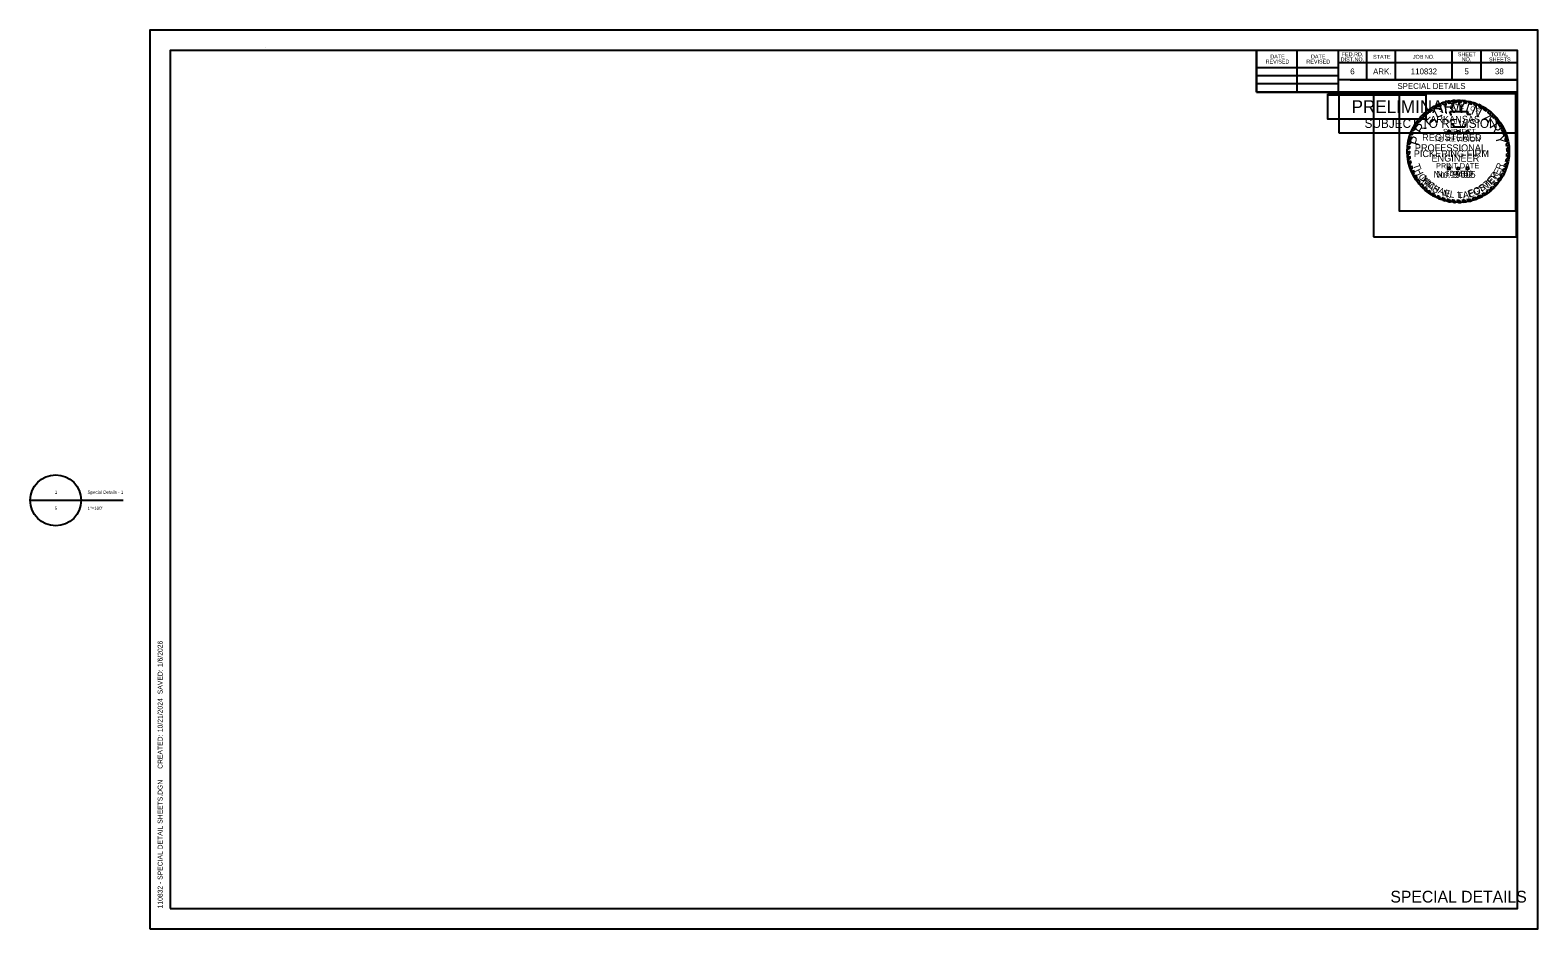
# Model space of a CAD drawing. Extents: x -0.12 to 1.42, y 0 to 0.92.
import ezdxf

# ---------------------------------------------------------------- set-up
doc = ezdxf.new("R2010")
doc.units = 0
for name, color, linetype in [('Default', 7, 'Continuous'), ('DSN_DRFT_Guideline-No-Plot', 7, 'Continuous'), ('SHET_Annotations', 7, 'Continuous'), ('SHET_Border-Lines', 7, 'Continuous'), ('SHET_Border-Text', 7, 'Continuous'), ('SHET_Stamp-Prelim', 7, 'Continuous'), ('SHET_Stamp-Seal', 7, 'Continuous'), ('STAMP_PE DIG SIG', 7, 'Continuous'), ('STAMP_PE_BACKGROUND', 7, 'Continuous'), ('STAMP_PE_FOSTER', 7, 'Continuous'), ('STAMP_PE_SEAL-INFO', 7, 'Continuous'), ('STAMP_PE_TAEGTMEYER', 7, 'Continuous'), ('STAMP_PRELIMINARY', 7, 'Continuous')]:
    doc.layers.add(name, color=color, linetype=linetype)

msp = doc.modelspace()

# ---------------------------------------------------------------- linework, layer by layer
at = {"layer": 'Default'}
for p, q in [((-0.1223, 0.4371), (-0.0702, 0.4371)), ((-0.096, 0.4371), (-0.0272, 0.4371))]:
    msp.add_line(p, q, dxfattribs=at)
msp.add_circle((-0.0962, 0.4371), 0.026, dxfattribs=at)
at = {"layer": 'DSN_DRFT_Guideline-No-Plot'}
msp.add_lwpolyline([(0, 0), (1.4167, 0), (1.4167, 0.9167), (0, 0.9167)], close=True, dxfattribs=at)
at = {"layer": 'SHET_Border-Lines'}
for p, q in [((0.1176, 0.8988), (0.1176, 0.8988)), ((0.1176, 0.8988), (0.1176, 0.8988)), ((1.1296, 0.8534), (1.1296, 0.8958)), ((1.1711, 0.8534), (1.1711, 0.8958)), ((1.2127, 0.8958), (1.2127, 0.8534)), ((1.2417, 0.8958), (1.2417, 0.866)), ((1.2712, 0.8958), (1.2712, 0.866)), ((1.3289, 0.8958), (1.3289, 0.866)), ((1.3584, 0.8958), (1.3584, 0.866)), ((1.1296, 0.8786), (1.2127, 0.8786)), ((1.3958, 0.8832), (1.2127, 0.8832)), ((1.3958, 0.8833), (1.3958, 0.8833)), ((1.1296, 0.8706), (1.2127, 0.8706)), ((1.1296, 0.8622), (1.2127, 0.8622)), ((1.3958, 0.866), (1.2127, 0.866)), ((1.2252, 0.866), (1.3958, 0.866)), ((1.3958, 0.8534), (1.1296, 0.8534))]:
    msp.add_line(p, q, dxfattribs=at)
for points in [[(0.0208, 0.0208), (1.3958, 0.0208), (1.3958, 0.8958), (0.0208, 0.8958)], [(1.1296, 0.8534), (1.3958, 0.8534), (1.3958, 0.8958), (1.1296, 0.8958)]]:
    msp.add_lwpolyline(points, close=True, dxfattribs=at)
at = {"layer": 'SHET_Stamp-Prelim'}
msp.add_lwpolyline([(1.2137, 0.8119), (1.3948, 0.8119), (1.3948, 0.8524), (1.2137, 0.8524)], close=True, dxfattribs=at)
at = {"layer": 'SHET_Stamp-Seal'}
msp.add_line((1.3219, 0.7895), (1.3219, 0.7895), dxfattribs=at)
msp.add_lwpolyline([(1.249, 0.7057), (1.3948, 0.7057), (1.3948, 0.8524), (1.249, 0.8524)], close=True, dxfattribs=at)
at = {"layer": 'STAMP_PE DIG SIG'}
msp.add_lwpolyline([(1.2022, 0.8508), (1.3022, 0.8508), (1.3022, 0.8258), (1.2022, 0.8258)], close=True, dxfattribs=at)
at = {"layer": 'STAMP_PE_BACKGROUND'}
for points in [[(1.2022, 0.8517), (1.3022, 0.8517), (1.3022, 0.8258), (1.2022, 0.8258)], [(1.3942, 0.8517), (1.275, 0.8517), (1.275, 0.7325), (1.3942, 0.7325)]]:
    msp.add_lwpolyline(points, close=True, dxfattribs=at)
at = {"layer": 'STAMP_PE_SEAL-INFO'}
for p, q in [((1.3002, 0.8313), (1.3028, 0.8306)), ((1.3021, 0.833), (1.3051, 0.8325)), ((1.3042, 0.8348), (1.3068, 0.8337)), ((1.3066, 0.8363), (1.309, 0.8352)), ((1.3087, 0.8377), (1.3112, 0.8365)), ((1.3112, 0.8391), (1.3138, 0.8378)), ((1.3137, 0.8403), (1.3158, 0.8387)), ((1.3165, 0.8415), (1.3181, 0.8397)), ((1.3184, 0.8422), (1.3206, 0.8405)), ((1.3217, 0.8432), (1.3233, 0.8413)), ((1.3239, 0.8438), (1.3259, 0.8418)), ((1.3266, 0.8443), (1.3283, 0.8422)), ((1.3269, 0.8337), (1.3456, 0.8337)), ((1.3276, 0.832), (1.3269, 0.8337)), ((1.3281, 0.8303), (1.3276, 0.832)), ((1.3295, 0.8447), (1.331, 0.8426)), ((1.3336, 0.8427), (1.3318, 0.8449)), ((1.3364, 0.8428), (1.3348, 0.845)), ((1.3389, 0.8426), (1.3375, 0.845)), ((1.3417, 0.8424), (1.3401, 0.8448)), ((1.3441, 0.842), (1.3427, 0.8445)), ((1.3456, 0.8337), (1.3443, 0.831)), ((1.3473, 0.8413), (1.3463, 0.8439)), ((1.3495, 0.8407), (1.3486, 0.8433)), ((1.352, 0.8399), (1.3512, 0.8426)), ((1.3544, 0.839), (1.3536, 0.8418)), ((1.357, 0.8379), (1.3564, 0.8406)), ((1.3594, 0.8366), (1.359, 0.8394)), ((1.3616, 0.8353), (1.3614, 0.8381)), ((1.364, 0.8337), (1.3639, 0.8366)), ((1.366, 0.8322), (1.3662, 0.8349)), ((1.3685, 0.8301), (1.3687, 0.8331)), ((1.3703, 0.8285), (1.3707, 0.8313)), ((1.2891, 0.8167), (1.2918, 0.8171)), ((1.2904, 0.8191), (1.2931, 0.8192)), ((1.2917, 0.8213), (1.2946, 0.8215)), ((1.293, 0.8232), (1.2959, 0.8232)), ((1.2946, 0.8253), (1.2977, 0.8254)), ((1.2965, 0.8276), (1.2994, 0.8274)), ((1.2983, 0.8295), (1.3014, 0.8293)), ((1.3282, 0.8297), (1.3281, 0.8303)), ((1.3293, 0.8201), (1.3291, 0.8213)), ((1.331, 0.8201), (1.3293, 0.8201)), ((1.331, 0.8177), (1.331, 0.8201)), ((1.3423, 0.8177), (1.331, 0.8177)), ((1.3424, 0.8196), (1.3423, 0.8177)), ((1.3429, 0.8213), (1.3424, 0.8196)), ((1.3443, 0.831), (1.3478, 0.831)), ((1.3478, 0.831), (1.347, 0.8297)), ((1.3723, 0.8264), (1.3727, 0.8294)), ((1.3738, 0.8247), (1.3746, 0.8273)), ((1.3756, 0.8223), (1.3764, 0.8251)), ((1.3769, 0.8206), (1.3779, 0.8232)), ((1.3786, 0.8178), (1.3796, 0.8205)), ((1.3797, 0.8157), (1.381, 0.8182)), ((1.381, 0.813), (1.3823, 0.8157)), ((1.2862, 0.8008), (1.2838, 0.7996)), ((1.2867, 0.8034), (1.2841, 0.802)), ((1.2847, 0.8048), (1.2873, 0.8059)), ((1.2853, 0.8071), (1.2879, 0.808)), ((1.2862, 0.8099), (1.2889, 0.8106)), ((1.287, 0.8121), (1.2898, 0.8129)), ((1.288, 0.8145), (1.2908, 0.8151)), ((1.3252, 0.8129), (1.3241, 0.8137)), ((1.3241, 0.8137), (1.3255, 0.8137)), ((1.3248, 0.8116), (1.3252, 0.8129)), ((1.3259, 0.8124), (1.3248, 0.8116)), ((1.3255, 0.8137), (1.3259, 0.815)), ((1.3259, 0.815), (1.3264, 0.8137)), ((1.327, 0.8116), (1.3259, 0.8124)), ((1.3264, 0.8137), (1.3277, 0.8137)), ((1.3277, 0.8137), (1.3266, 0.8129)), ((1.3266, 0.8129), (1.327, 0.8116)), ((1.3347, 0.8129), (1.3336, 0.8137)), ((1.3336, 0.8137), (1.335, 0.8137)), ((1.3343, 0.8116), (1.3347, 0.8129)), ((1.3354, 0.8124), (1.3343, 0.8116)), ((1.335, 0.8137), (1.3354, 0.815)), ((1.3354, 0.815), (1.3358, 0.8137)), ((1.3365, 0.8116), (1.3354, 0.8124)), ((1.3358, 0.8137), (1.3372, 0.8137)), ((1.3372, 0.8137), (1.3361, 0.8129)), ((1.3361, 0.8129), (1.3365, 0.8116)), ((1.3442, 0.8129), (1.3431, 0.8137)), ((1.3431, 0.8137), (1.3445, 0.8137)), ((1.3438, 0.8116), (1.3442, 0.8129)), ((1.3449, 0.8124), (1.3438, 0.8116)), ((1.3445, 0.8137), (1.3449, 0.815)), ((1.3449, 0.815), (1.3453, 0.8137)), ((1.346, 0.8116), (1.3449, 0.8124)), ((1.3453, 0.8137), (1.3467, 0.8137)), ((1.3467, 0.8137), (1.3456, 0.8129)), ((1.3456, 0.8129), (1.346, 0.8116)), ((1.3818, 0.8112), (1.3832, 0.8136)), ((1.3829, 0.8081), (1.3844, 0.8107)), ((1.3835, 0.8061), (1.3851, 0.8086)), ((1.3842, 0.8029), (1.386, 0.8054)), ((1.3846, 0.8008), (1.3866, 0.8028)), ((1.2857, 0.796), (1.2834, 0.7946)), ((1.2856, 0.7933), (1.2834, 0.7914)), ((1.2859, 0.7984), (1.2835, 0.7968)), ((1.2857, 0.791), (1.2835, 0.7892)), ((1.2858, 0.7882), (1.2838, 0.7862)), ((1.2861, 0.7858), (1.2842, 0.7837)), ((1.3846, 0.7855), (1.3871, 0.7867)), ((1.3849, 0.7876), (1.3874, 0.7891)), ((1.385, 0.798), (1.387, 0.7998)), ((1.3851, 0.7956), (1.3873, 0.7973)), ((1.3852, 0.7927), (1.3875, 0.7945)), ((1.3852, 0.7905), (1.3875, 0.792)), ((1.2866, 0.7833), (1.2847, 0.7812)), ((1.2871, 0.7809), (1.2854, 0.7786)), ((1.2878, 0.7784), (1.2861, 0.7761)), ((1.2886, 0.7761), (1.287, 0.7738)), ((1.2895, 0.7737), (1.288, 0.7713)), ((1.2905, 0.7715), (1.2892, 0.769)), ((1.3252, 0.7754), (1.3241, 0.7763)), ((1.3241, 0.7763), (1.3255, 0.7763)), ((1.3248, 0.7741), (1.3252, 0.7754)), ((1.3259, 0.7749), (1.3248, 0.7741)), ((1.3255, 0.7763), (1.3259, 0.7776)), ((1.3259, 0.7776), (1.3264, 0.7763)), ((1.327, 0.7741), (1.3259, 0.7749)), ((1.3264, 0.7763), (1.3277, 0.7763)), ((1.3277, 0.7763), (1.3266, 0.7754)), ((1.3266, 0.7754), (1.327, 0.7741)), ((1.3347, 0.7754), (1.3336, 0.7763)), ((1.3336, 0.7763), (1.335, 0.7763)), ((1.3343, 0.7741), (1.3347, 0.7754)), ((1.3354, 0.7749), (1.3343, 0.7741)), ((1.335, 0.7763), (1.3354, 0.7776)), ((1.3354, 0.7776), (1.3358, 0.7763)), ((1.3365, 0.7741), (1.3354, 0.7749)), ((1.3358, 0.7763), (1.3372, 0.7763)), ((1.3372, 0.7763), (1.3361, 0.7754)), ((1.3361, 0.7754), (1.3365, 0.7741)), ((1.3442, 0.7754), (1.3431, 0.7763)), ((1.3431, 0.7763), (1.3445, 0.7763)), ((1.3438, 0.7741), (1.3442, 0.7754)), ((1.3449, 0.7749), (1.3438, 0.7741)), ((1.3445, 0.7763), (1.3449, 0.7776)), ((1.3449, 0.7776), (1.3453, 0.7763)), ((1.346, 0.7741), (1.3449, 0.7749)), ((1.3453, 0.7763), (1.3467, 0.7763)), ((1.3467, 0.7763), (1.3456, 0.7754)), ((1.3456, 0.7754), (1.346, 0.7741)), ((1.3799, 0.7705), (1.3826, 0.7709)), ((1.3808, 0.7724), (1.3835, 0.7729)), ((1.382, 0.7753), (1.3847, 0.776)), ((1.3827, 0.7774), (1.3855, 0.7785)), ((1.3835, 0.7802), (1.3862, 0.7813)), ((1.3841, 0.7827), (1.3867, 0.7838)), ((1.2918, 0.769), (1.2907, 0.7662)), ((1.2931, 0.7667), (1.2921, 0.7641)), ((1.2942, 0.765), (1.2936, 0.7619)), ((1.2958, 0.7628), (1.2952, 0.7598)), ((1.2975, 0.7607), (1.297, 0.7578)), ((1.2992, 0.7588), (1.2988, 0.7559)), ((1.301, 0.757), (1.3008, 0.754)), ((1.3029, 0.7552), (1.3029, 0.7523)), ((1.3679, 0.7553), (1.3706, 0.7545)), ((1.3702, 0.7573), (1.3727, 0.7566)), ((1.3716, 0.7588), (1.3743, 0.7583)), ((1.3738, 0.7612), (1.3763, 0.7608)), ((1.3755, 0.7634), (1.3783, 0.7634)), ((1.3774, 0.7662), (1.3801, 0.7661)), ((1.3783, 0.7677), (1.3811, 0.768)), ((1.3049, 0.7536), (1.305, 0.7507)), ((1.3068, 0.7522), (1.307, 0.7493)), ((1.3092, 0.7506), (1.3095, 0.7478)), ((1.3111, 0.7495), (1.3117, 0.7466)), ((1.3138, 0.7481), (1.3147, 0.7452)), ((1.3159, 0.7471), (1.3169, 0.7443)), ((1.3187, 0.7461), (1.3198, 0.7433)), ((1.321, 0.7453), (1.3222, 0.7426)), ((1.3238, 0.7445), (1.325, 0.7419)), ((1.326, 0.7441), (1.3274, 0.7415)), ((1.3288, 0.7436), (1.3302, 0.7411)), ((1.3313, 0.7433), (1.3328, 0.7409)), ((1.334, 0.7432), (1.3356, 0.7409)), ((1.3365, 0.7432), (1.3384, 0.741)), ((1.3394, 0.7433), (1.3412, 0.7412)), ((1.3419, 0.7436), (1.344, 0.7416)), ((1.3444, 0.744), (1.3465, 0.7421)), ((1.3471, 0.7446), (1.3492, 0.7427)), ((1.3497, 0.7453), (1.352, 0.7436)), ((1.3524, 0.7462), (1.3549, 0.7447)), ((1.3548, 0.7471), (1.3571, 0.7456)), ((1.3573, 0.7483), (1.36, 0.7471)), ((1.3596, 0.7494), (1.3619, 0.7481)), ((1.3619, 0.7508), (1.3644, 0.7497)), ((1.3639, 0.7521), (1.3663, 0.751)), ((1.3664, 0.754), (1.369, 0.7532))]:
    msp.add_line(p, q, dxfattribs=at)
for radius, start, end in [(0.0521, 129.7326, 132.5376), (0.0498, 127.5297, 130.9683), (0.0521, 123.6199, 126.5906), (0.0498, 121.9746, 125.11), (0.0521, 117.6544, 120.8099), (0.0498, 115.6869, 119.1583), (0.0521, 111.3124, 114.7026), (0.0498, 110.3086, 113.1659), (0.0521, 105.2339, 109.0352), (0.0498, 104.0352, 107.3615), (0.0521, 99.7525, 102.7765), (0.0498, 98.258, 101.0329), (0.0521, 93.9381, 96.5517), (0.0498, 92.1102, 95.0367), (0.0521, 87.7298, 90.6707), (0.0498, 85.9628, 88.9097), (0.0521, 81.9732, 84.8236), (0.0498, 79.9264, 82.696), (0.0521, 75.3125, 77.9426), (0.0498, 73.5575, 76.2314), (0.0521, 69.6061, 72.3058), (0.0498, 67.6248, 70.504), (0.0521, 63.1329, 66.2704), (0.0498, 61.1558, 64.3784), (0.0521, 56.9003, 60.0942), (0.0498, 54.9238, 58.2702), (0.0498, 48.3016, 52.0395), (0.0521, 50.3492, 53.7159), (0.0521, 44.3405, 47.3929), (0.0521, 152.864, 155.5189), (0.0521, 147.0072, 149.899), (0.0498, 151.0315, 153.573), (0.0521, 141.6056, 144.4486), (0.0498, 145.0197, 148.2104), (0.0498, 139.301, 142.5873), (0.0521, 135.4021, 138.3031), (0.0498, 133.1331, 136.2562), (0.0498, 42.2212, 45.5512), (0.0498, 36.135, 39.5311), (0.0521, 38.1247, 41.2316), (0.0498, 29.9032, 33.6645), (0.0521, 31.9614, 35.4294), (0.0498, 23.7732, 27.2211), (0.0521, 25.9391, 29.0125), (0.0521, 170.0003, 172.6878), (0.0521, 164.3068, 166.894), (0.0521, 158.4077, 161.0701), (0.0498, 167.9048, 170.9039), (0.0498, 162.4331, 165.0013), (0.0498, 156.3402, 159.2319), (0.0498, 17.6802, 21.4251), (0.0521, 19.9538, 23.3141), (0.0498, 11.5444, 15.2364), (0.0498, 5.7599, 9.0606), (0.0521, 13.8421, 17.4447), (0.0521, 7.5852, 10.8621), (0.0521, 175.7409, 178.2066), (0.0521, 181.7251, 184.1626), (0.0521, 187.4204, 190.1927), (0.0498, 179.6454, 182.2633), (0.0498, 173.73, 176.4734), (0.0498, 185.4539, 188.234), (0.0498, 348.0778, 351.3435), (0.0498, 353.8632, 357.1274), (0.0498, 359.7329, 3.0639), (0.0521, 349.8305, 353.0885), (0.0521, 1.7215, 4.7268), (0.0521, 355.7156, 358.9569), (0.0521, 193.0369, 195.9973), (0.0521, 198.8967, 201.6281), (0.0498, 191.2274, 193.9858), (0.0498, 196.9675, 199.8353), (0.0521, 204.5479, 207.4328), (0.0498, 202.7761, 205.4791), (0.0498, 329.5549, 333.2076), (0.0498, 335.6038, 339.1858), (0.0521, 331.4037, 334.9332), (0.0498, 341.777, 345.0925), (0.0521, 337.3837, 340.9933), (0.0521, 343.8925, 347.035), (0.0521, 210.8636, 213.6571), (0.0498, 208.7883, 211.7934), (0.0521, 216.6115, 219.491), (0.0498, 214.1838, 217.2747), (0.0521, 222.48, 225.3801), (0.0498, 220.3909, 223.3056), (0.0498, 226.2494, 229.2407), (0.0498, 310.7744, 314.3161), (0.0521, 312.4518, 315.6633), (0.0498, 316.6531, 320.3711), (0.0521, 318.2846, 321.8043), (0.0498, 323.5851, 327.4407), (0.0521, 325.4405, 328.9872), (0.0521, 228.3665, 231.348), (0.0498, 232.229, 234.9336), (0.0521, 234.295, 236.9452), (0.0498, 238.2223, 240.8353), (0.0521, 240.1977, 242.8613), (0.0498, 244.3204, 246.9486), (0.0521, 246.576, 249.1558), (0.0498, 250.3491, 253.1216), (0.0521, 252.5967, 255.3252), (0.0498, 256.505, 259.1192), (0.0521, 258.4433, 261.1398), (0.0498, 262.3783, 265.2012), (0.0521, 264.1978, 267.1009), (0.0498, 268.3215, 271.277), (0.0521, 270.2548, 273.3361), (0.0498, 274.6157, 277.4486), (0.0521, 276.4239, 279.4357), (0.0498, 280.3459, 283.5814), (0.0521, 282.3199, 285.3702), (0.0498, 286.6423, 289.9783), (0.0521, 288.5709, 291.9733), (0.0498, 292.8745, 296.1185), (0.0521, 294.6481, 298.2166), (0.0498, 299.0768, 302.1724), (0.0521, 300.621, 303.8703), (0.0498, 304.823, 308.5143), (0.0521, 306.3721, 310.208)]:
    msp.add_arc((1.3354, 0.793), radius, start, end, dxfattribs=at)
at = {"layer": 'STAMP_PRELIMINARY'}
msp.add_circle((1.3354, 0.793), 0.0521, dxfattribs=at)

# ---------------------------------------------------------------- texts
at = {"layer": 'Default'}
for s, height, p in [('1', 0.00328, (-0.0971, 0.4437)), ('Special Details - 1', 0.003281, (-0.0637, 0.4437)), ('5', 0.00328, (-0.0972, 0.4273)), ('1"=100\'', 0.00328, (-0.0637, 0.4273))]:
    msp.add_text(s, height=height, dxfattribs=at).set_placement(p)
at = {"layer": 'SHET_Annotations'}
for s, height, p in [('6', 0.006, (1.2252, 0.8716)), ('ARK.', 0.006, (1.2485, 0.8716)), ('110832', 0.006, (1.287, 0.8716)), ('5', 0.006, (1.3418, 0.8716)), ('38', 0.006, (1.3729, 0.8717)), ('SPECIAL DETAILS', 0.006, (1.2733, 0.8567)), ('SPECIAL DETAILS', 0.012, (1.2662, 0.0268))]:
    msp.add_text(s, height=height, dxfattribs=at).set_placement(p)
at = {"layer": 'SHET_Border-Text'}
for s, p in [('FED.RD.', (1.2165, 0.8901)), ('SHEET', (1.335, 0.8901)), ('TOTAL', (1.3686, 0.8901)), ('REVISED', (1.1388, 0.8826)), ('DATE', (1.1436, 0.8878)), ('REVISED', (1.1804, 0.8826)), ('DATE', (1.1851, 0.8878)), ('DIST.NO.', (1.2154, 0.8849)), ('STATE', (1.2485, 0.8875)), ('JOB NO.', (1.2891, 0.8875)), ('NO.', (1.339, 0.8849)), ('SHEETS', (1.3668, 0.8849))]:
    msp.add_text(s, height=0.004, dxfattribs=at).set_placement(p)
for s, p in [('1/6/2026', (0.0129, 0.267)), ('  SAVED: ', (0.0129, 0.2355)), ('10/21/2024', (0.0129, 0.2006)), ('     CREATED: ', (0.0129, 0.1536)), ('110832 - SPECIAL DETAIL SHEETS.DGN', (0.0129, 0.0208))]:
    msp.add_text(s, height=0.005, rotation=90, dxfattribs=at).set_placement(p)
at = {"layer": 'SHET_Stamp-Prelim'}
for s, height, p in [('PRELIMINARY', 0.013, (1.2266, 0.8322)), ('SUBJECT TO REVISION', 0.009, (1.2398, 0.817))]:
    msp.add_text(s, height=height, dxfattribs=at).set_placement(p)
at = {"layer": 'STAMP_PE_FOSTER'}
msp.add_text('No. 9402', height=0.00698, dxfattribs=at).set_placement((1.313, 0.7661))
for s, rotation, p in [('R', 54.5031, (1.373, 0.764)), ('M', 308.339, (1.297, 0.7652)), ('I', 314.1842, (1.3014, 0.7599)), ('C', 319.8733, (1.3034, 0.7579)), ('H', 327.7235, (1.3086, 0.7538)), ('A', 335.7276, (1.3141, 0.7506)), ('E', 343.5779, (1.3204, 0.748)), ('F', 15.8691, (1.3468, 0.7469)), ('O', 23.719, (1.3526, 0.7487)), ('S', 31.7234, (1.3588, 0.7517)), ('T', 39.4194, (1.3641, 0.7552)), ('E', 46.9613, (1.3689, 0.7594)), ('L', 350.8115, (1.3263, 0.7464)), ('L', 1.2666, (1.3349, 0.7455)), ('.', 6.8035, (1.3408, 0.7459))]:
    msp.add_text(s, height=0.0067, rotation=rotation, dxfattribs=at).set_placement(p)
at = {"layer": 'STAMP_PE_SEAL-INFO'}
for s, rotation, p in [('S', 23.5541, (1.3164, 0.8327)), ('T', 16.311, (1.3216, 0.8347)), ('A', 9.0679, (1.3269, 0.8361)), ('T', 1.8248, (1.3325, 0.8369)), ('E', 355.2002, (1.3375, 0.8369)), ('O', 342.2506, (1.3472, 0.8354)), ('F', 335.0075, (1.3526, 0.8335))]:
    msp.add_text(s, height=0.00436, rotation=rotation, dxfattribs=at).set_placement(p)
for s, height, p in [('ARKANSAS', 0.00698, (1.3069, 0.8223)), ('PROFESSIONAL', 0.006983, (1.2911, 0.7932)), ('REGISTERED', 0.00698, (1.2986, 0.8038)), ('ENGINEER', 0.00698, (1.3081, 0.7826))]:
    msp.add_text(s, height=height, dxfattribs=at).set_placement(p)
at = {"layer": 'STAMP_PE_TAEGTMEYER'}
for s, rotation, p in [('T', 289.646, (1.289, 0.7791)), ('H', 296.7339, (1.291, 0.7736)), ('O', 303.7708, (1.2943, 0.7674)), ('Y', 53.9986, (1.3733, 0.7628)), ('E', 63.0984, (1.377, 0.768)), ('R', 69.57, (1.3798, 0.7735)), ('M', 314.2033, (1.298, 0.7621)), ('A', 321.0594, (1.3034, 0.7567)), ('S', 327.8239, (1.308, 0.7531)), ('G', 23.3052, (1.3522, 0.7475)), ('T', 31.466, (1.3583, 0.7503)), ('M', 39.3, (1.3633, 0.7533)), ('E', 46.8094, (1.3692, 0.7582)), ('N', 344.2727, (1.3186, 0.7474)), ('.', 350.6464, (1.3254, 0.7456)), ('T', 3.0061, (1.3347, 0.7445)), ('A', 8.9826, (1.3405, 0.7448)), ('E', 17.6836, (1.3463, 0.7457))]:
    msp.add_text(s, height=0.00698, rotation=rotation, dxfattribs=at).set_placement(p)
msp.add_text('No. 19605', height=0.00698, dxfattribs=at).set_placement((1.3101, 0.7661))
at = {"layer": 'STAMP_PRELIMINARY'}
for s, rotation, p in [('E', 42.3578, (1.3048, 0.8192)), ('L', 25.513, (1.3131, 0.8266)), ('I', 12.5248, (1.3217, 0.8309)), ('M', 3.1074, (1.3278, 0.8326)), ('I', 342.3164, (1.3416, 0.833)), ('N', 333.9382, (1.3478, 0.8315)), ('R', 56.2292, (1.2984, 0.8095)), ('A', 315.6579, (1.3591, 0.8257)), ('R', 301.3831, (1.3668, 0.8184)), ('P', 73.913, (1.2953, 0.7982)), ('Y', 283.2593, (1.3729, 0.8084))]:
    msp.add_text(s, height=0.0101, rotation=rotation, dxfattribs=at).set_placement(p)
for s, height, p in [('SUBJECT', 0.00536, (1.3198, 0.8106)), ('TO REVISION', 0.005363, (1.3105, 0.8028)), ('PICKERING FIRM', 0.006983, (1.29, 0.7872)), ('PRINT DATE', 0.00536, (1.3128, 0.7757)), ('$DATE$', 0.00536, (1.3222, 0.768))]:
    msp.add_text(s, height=height, dxfattribs=at).set_placement(p)

doc.saveas('drawing.dxf')
